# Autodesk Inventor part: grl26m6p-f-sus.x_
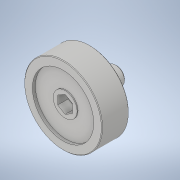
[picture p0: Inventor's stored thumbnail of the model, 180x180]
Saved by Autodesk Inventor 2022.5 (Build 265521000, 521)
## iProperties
Created: 2021-02
Part Number: grl26m6p-f-sus.x_
Material: 一般
Document SubType Name: Modeling
Designer: ImaoCorp
Density: 1 g/cm^3
Appearance: 既定
Sending System: SOLIDWORKS 2019-2019304
MC: AMD64
MC_MODEL: Intel64 Family 6 Model 60 Stepping 3, GenuineIntel
OS: Windows_NT
FRU: Parasolid Version 31.0, build 290,  9- 1-2019
FORMAT: text
GUISE: transmit
KEY: grl26m6p-f-sus
FILE: grl26m6p-f-sus.x_t
DATE: Mon Feb 22 15:02:30 2021
Author: ImaoCorp
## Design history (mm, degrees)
feature "Base1"
node "ソリッド1"
